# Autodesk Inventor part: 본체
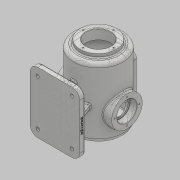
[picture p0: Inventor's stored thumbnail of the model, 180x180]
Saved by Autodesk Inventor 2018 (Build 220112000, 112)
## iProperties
Created: 2021-11
Part Number: 본체
Material: 일반
Document SubType Name: Modeling
Designer: home
Density: 1 g/cm^3
Appearance: 기본값
Author: home
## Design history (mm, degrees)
sketch "스케치1"
  geometry: L1 (-45, -80)-(45, -80); L2 (65, -60)-(65, 60); L3 (45, 80)-(-45, 80); L4 (-65, 60)-(-65, -60); L5 (-65, -80)-(65, 80); L6 (65, -80)-(-65, 80); A1 r 20 centre (45, 60) between (65, 60) and (45, 80); A2 r 20 centre (45, -60) between (45, -80) and (65, -60); A3 r 20 centre (-45, -60) between (-65, -60) and (-45, -80); A4 r 20 centre (-45, 60) between (-45, 80) and (-65, 60); 1 further point
  constraints: 12 end point, 8 point on circle, 8 point on line, 8 tangent, 4 centre point, 3 equal radius, 2 midpoint, 2 parallel, 1 horizontal, 1 perpendicular
  dimensions: "d0" = 130 distance of L6.end L5.end; "d1" = 160 distance of L5.end L6.start; "d2" = 20 radius of A1
extrude "돌출1" new body sketch "스케치1" distance "d4" = 14; taper "d5" = 0 deg
sketch "스케치2"
  geometry: L1 (-45, -80)-(45, -80) reference; A1 r 20 centre (-45, -60) between (-65, -60) and (-45, -80) reference; A2 r 20 centre (45, -60) between (45, -80) and (65, -60) reference; A3 r 20 centre (45, 60) between (65, 60) and (45, 80) reference; A4 r 20 centre (-45, 60) between (-45, 80) and (-65, 60) reference; 1 further point
hole "구멍1" sketch "스케치2" at (-45, -60), (45, -60), (-45, 60), (45, 60) diameter "d6" = 9; stored, may be unused: countersink angle "d10" = 90 deg, drill point angle "d12" = 118 deg; dims "d7" = 6, "d8" = 18, "d9" = 2, "d11" = 8
node "작업 평면1"
sketch "스케치3"
  geometry: L1 (0, -80)-(0, -110); L2 (-47.5, -110)-(-47.5, -100); L3 (-47.5, -100)-(-55, -100); L4 (-65, -90)-(-65, 71.239); L5 (0, -110)-(0, 100); L6 (-47.5, -110)-(-32.5, -110); L7 (-32.5, -110)-(-32.5, -85); L8 (-32.5, -85)-(-52, -85); L9 (-55, -82)-(-55, 69.75); A1 r 100 centre (0, 0) between (0, 100) and (-61.111, 79.154); A2 r 90 centre (0, 0) between (0, 90) and (-53.793, 72.155); A3 r 10 centre (-55, -90) between (-65, -90) and (-55, -100); A4 r 10 centre (-55, 71.239) between (-61.111, 79.154) and (-65, 71.239); A5 r 3 centre (-52, 69.75) between (-53.793, 72.155) and (-55, 69.75); A6 r 3 centre (-52, -82) between (-55, -82) and (-52, -85); 5 further points
  constraints: 18 end point, 14 point on circle, 9 tangent, 7 point on line, 6 centre point, 4 vertical, 2 coincident, 2 equal radius, 2 parallel, 2 perpendicular, 1 horizontal
  dimensions: "d14" = 30 distance of L1.start L1.end; "d15" = 47.5 distance of L1.end L2.start; "d16" = 10 distance of L2.start L2.end; "d17" = 17.5 distance of L2.end point (-65, -100); "d23" = 200 diameter of A1; "d24" = 210 distance of L5.end L1.end; "d26" = 32.5 distance of L1.end L6.end; "d27" = 25 distance of L6.end L7.end; "d28" = 22.5 distance of L7.end point (-55, -85); "d29" = 180 diameter of A2; "d30" = 0 distance from line of point (0, 0) L1; "d32" = 10 radius of A3; "d33" = 3 radius of A5
revolve "회전1" sketch "스케치3" stored, may be unused: angle "d31" = 90 deg
node "작업 평면2"
sketch "스케치6"
  geometry: L1 (-47.5, 100.62)-(47.5, 100.62) reference; L2 (0, 100.62)-(0, -26.38); C1 r 40 at (0, -26.38); 1 further point
  constraints: 2 end point, 1 centre point, 1 coincident, 1 midpoint, 1 vertical
  dimensions: "d40" = 127 distance of L2.start L2.end; "d41" = 80 diameter of C1
extrude "돌출2" join sketch "스케치6" stored distance "d42" = 0; taper "d43" = 0 deg
sketch "스케치7"
  geometry: C1 r 40 at (26.38, 0); A1 r 40 centre (26.38, 0) between (66.38, 0) and (-13.62, 0) reference; 1 further point
  constraints: 1 centre point, 1 coincident
  dimensions: "d44" = 80 diameter of C1
extrude "돌출3" join sketch "스케치7" distance "d45" = 10; taper "d46" = 0 deg
hole "구멍2" diameter "d49" = 52; stored, may be unused: countersink angle "d53" = 90 deg, drill point angle "d55" = 0 deg; dims "d47" = 10, "d48" = 10, "d50" = 6, "d51" = 52, "d52" = 18, "d54" = 18
hole "구멍3" diameter "d58" = 42; stored, may be unused: countersink angle "d62" = 90 deg, drill point angle "d64" = 0 deg; dims "d56" = 10, "d57" = 10, "d59" = 6, "d60" = 52, "d61" = 18, "d63" = 18
node "작업 평면3"
sketch "스케치8"
  geometry: L1 (47.5, -110)-(-47.5, -110) reference; L2 (0, -110)-(0, -60); L3 (0, -60)-(-15, -60); L4 (-30, -45)-(-30, 45); L5 (55, 69.75)-(-55, 69.75) reference; L6 (-15, 60)-(15, 60); L7 (30, 45)-(30, -45); L8 (15, -60)-(0, -60); A1 r 15 centre (-15, -45) between (-30, -45) and (-15, -60); A2 r 15 centre (15, -45) between (15, -60) and (30, -45); A3 r 15 centre (15, 45) between (30, 45) and (15, 60); A4 r 15 centre (-15, 45) between (-15, 60) and (-30, 45); 5 further points
  constraints: 12 end point, 8 point on circle, 8 point on line, 8 tangent, 4 centre point, 3 equal radius, 3 perpendicular, 1 horizontal, 1 midpoint, 1 vertical
  dimensions: "d66" = 50 distance of L2.start L2.end; "d67" = 30 distance of L2.end point (-30, -60); "d68" = 120 distance of point (-30, -60) point (-30, 60); "d70" = 60 distance of point (-30, 60) point (30, 60); "d71" = 120 distance of point (30, 60) point (30, -60); "d72" = 15 radius of A1
extrude "돌출4" join sketch "스케치8" stored distance "d73" = 10; taper "d74" = 0 deg
sketch "스케치9"
  geometry: L1 (-20, -45)-(-20, 45); L2 (-15, 50)-(15, 50); L3 (-15, -50)-(15, -50); L4 (20, -45)-(20, 45); L5 (-30, 45)-(-30, -45) reference; L6 (30, -45)-(30, 45) reference; L7 (-15, -60)-(15, -60) reference; L8 (15, 60)-(-15, 60) reference; A1 r 5 centre (-15, -45) between (-20, -45) and (-15, -50); A2 r 5 centre (15, -45) between (15, -50) and (20, -45); A3 r 5 centre (15, 45) between (20, 45) and (15, 50); A4 r 5 centre (-15, 45) between (-15, 50) and (-20, 45); 1 further point
  constraints: 8 end point, 8 point on circle, 8 tangent, 4 centre point, 3 equal radius, 2 horizontal, 2 vertical
  dimensions: "d75" = 10 distance between parallel lines of L1 L5; "d76" = 10 distance between parallel lines of L6 L4; "d77" = 10 distance between parallel lines of L7 L3; "d78" = 10 distance between parallel lines of L8 L2; "d79" = 5 radius of A1
extrude "돌출5" cut sketch "스케치9" stored distance "d80" = 10; taper "d81" = 0 deg
sketch "스케치10"
  geometry: L1 (-15, -60)-(15, -60) reference; L2 (15, 60)-(-15, 60) reference; L3 (0, -60)-(0, -55); L4 (0, 60)-(0, 55); L5 (0, 0)-(-25, 0); L6 (0, 0)-(25, 0)
  constraints: 8 end point, 2 midpoint, 1 parallel, 1 point on line, 1 vertical
  dimensions: "d82" = 5 distance of L3.start L3.end; "d83" = 5 distance of L4.start L4.end; "d84" = 55 distance of L4.end L5.start (derived); "d85" = 25 distance of L5.start L5.end; "d86" = 25 distance of L5.start L6.end; "d87" = 90 deg angle of L2 L3
hole "구멍4" sketch "스케치10" at (25, 0), (-25, 0), (0, -55), (0, 55) diameter "d88" = 3.242; stored, may be unused: countersink angle "d92" = 90 deg, drill point angle "d94" = 118 deg; dims "d89" = 9, "d90" = 52, "d91" = 18, "d93" = 11
sketch "스케치11"
  geometry: L1 (0, 32.5)-(0, -32.5); L2 (32.5, 0)-(-32.5, 0); C1 r 40 at (0, 0) reference; A1 r 32.5 centre (0, 0) between (0, 32.5) and (0, -32.5); 1 further point
  constraints: 4 end point, 4 point on circle, 1 centre point, 1 coincident, 1 perpendicular, 1 vertical
  dimensions: "d95" = 65 diameter of A1; "d96" = 0 distance from line of C1.centre L2; "d97" = 0 distance from line of C1.centre L1
hole "구멍5" sketch "스케치11" at (0, 32.5), (-32.5, 0), (0, -32.5), (32.5, 0) diameter "d98" = 3.242; stored, may be unused: countersink angle "d102" = 90 deg, drill point angle "d104" = 118 deg; dims "d99" = 11, "d100" = 52, "d101" = 18, "d103" = 13
sketch "스케치12"
  geometry: L1 (0, 40)-(0, -40); L2 (40, 0)-(-40, 0); C1 r 47.5 at (0, 0) reference; A1 r 40 centre (0, 0) between (0, 40) and (0, -40); 1 further point
  constraints: 4 end point, 4 point on circle, 1 centre point, 1 coincident, 1 perpendicular, 1 vertical
  dimensions: "d105" = 80 diameter of A1; "d106" = 0 distance from line of C1.centre L2; "d107" = 0 distance from line of C1.centre L1
hole "구멍6" sketch "스케치12" at (0, 40), (40, 0), (0, -40), (-40, 0) diameter "d108" = 3.242; stored, may be unused: countersink angle "d112" = 90 deg, drill point angle "d114" = 118 deg; dims "d109" = 11, "d110" = 52, "d111" = 18, "d113" = 13
sketch "스케치16"
  geometry: L1 (-50, 14)-(-33.809, 58.485); L2 (65, 0)-(65, 14) reference; L3 (50, 14)-(33.809, 58.485); L4 (-45, 14)-(-65, 14) reference; C1 r 61.111 at (0, 114) reference; A1 r 65 centre (0, 114) between (-33.809, 58.485) and (33.809, 58.485); 2 further points
  constraints: 4 end point, 2 point on circle, 1 centre point, 1 coincident, 1 tangent
  dimensions: "d142" = 15 distance of L2.end L3.start; "d147" = 110 deg angle of L4 L1; "d148" = 20 deg angle of L2 L3; "d149" = 14.09539 distance from line of L2.end L3; "d153" = 115 distance from line of L1.start L2; "d154" = 108.06465 distance from line of L2.end L1
feature "리브3" sketch "스케치16" dims "d155" = 1, "d156" = 14, "d157" = 0, "d158" = 0, "d159" = 1, "d160" = 1
sketch "스케치17"
  geometry: L1 (14, 60)-(14, 80) reference; L2 (14, 80)-(14, 60); L3 (0, -80)-(14, -80) reference; L4 (14, -80)-(14, -60) reference; L5 (14, -80)-(14, -60); L6 (14, -60)-(50.452, -46.733); L7 (14, 60)-(50.852, 46.587); L8 (50.852, 46.587)-(50.452, -46.733); 1 further point
  constraints: 10 end point, 1 collinear, 1 vertical
  dimensions: "d161" = 20 distance of L1.end L1.start (derived); "d162" = 20 distance of L3.end L4.end (derived); "d163" = 110 deg angle of L1 L7; "d164" = 110 deg angle of L4 L6; "d165" = 90.2459 deg angle of L3 L8; "d166" = 36.99529 distance from line of L1.end L8
feature "리브4" sketch "스케치17" dims "d167" = 1, "d168" = 14, "d169" = 0, "d170" = 0, "d171" = 1, "d172" = 1
chamfer "모따기1" distance "d173" = 1; stored, may be unused: second distance "d174" = 2, angle "d175" = 45 deg
fillet "모깎기1" dims "d176" = 0.3, "d177" = 3
sketch "스케치18"
  geometry: L1 (0, 0)-(0, 11) reference; L2 (0, 5.5)-(120, 5.5); L3 (60, 0)-(60, 11); L4 (39.545, 8.353)-(81.024, 8.353); L5 (81.024, 8.353)-(81.024, 2.349); L6 (81.024, 2.349)-(39.545, 2.349); L7 (39.545, 2.349)-(39.545, 8.353)
  constraints: 4 end point, 1 horizontal, 1 midpoint, 1 parallel, 1 vertical, 2 other
  dimensions: "d178" = 81.02373 distance between parallel lines of L1 L5; "d179" = 39.54476 distance between parallel lines of L1 L7; "d180" = 6.00407 distance between parallel lines of L4 L6; "d181" = 2.85328 distance between parallel lines of L2 L4; "d182" = 120 distance from line of L2.end L1; "d183" = 2.64672 distance from line of L3.end L4
feature "엠보싱1" sketch "스케치18" dims "d0" = 130, "d1" = 160, "d2" = 20, "d184" = 0.5, "d185" = 0
node "솔리드1"
mirror "미러1"
mirror "미러2"
mirror "미러3"
